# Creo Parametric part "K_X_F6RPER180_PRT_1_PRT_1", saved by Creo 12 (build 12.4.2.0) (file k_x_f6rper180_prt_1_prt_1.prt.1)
Units: Custom; MM, KILOGRAM, SECS

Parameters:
  PTC_WM_ITERATION = "0"
  PTC_WM_VERSION = "-.0"
  PTC_WM_LIFECYCLE_STATE = "In Work"
  PTC_WM_LIFECYCLE = "MO_CADDocument"
  PTC_WM_CREATED_BY = "Maximilian Roepper (Z0017RMS: MO)"
  PTC_WM_CREATED_ON = "18-Sep-26 11:36:42 AM"
  PTC_WM_MODIFIED_BY = "Maximilian Roepper (Z0017RMS: MO)"
  PTC_WM_MODIFIED_ON = "18-Sep-26 11:36:46 AM"
  PDMLINKNUMBER = "PDM000071454890"
  PTC_WM_NAME = "k_x_f6rper180_prt_1_prt_1.prt"
  PTC_WM_NUMBER = "PDM000071454890"

Other parameters: WEIGHT, WEIGHT_FACTOR, WEIGHT_ADD, _MASS_TEMP, _DIFF_TEMP, MC_ERRORS, SUPPLIER

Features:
  1. coordinate system
  2. datum plane "PRT_YZ"
  3. datum plane "PRT_XY"
  4. datum plane "PRT_XZ"
  5. coordinate system
  6. datum axis
  7. datum axis
  8. datum axis
  9. coordinate system
  10. imported feature
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
Other named items: PRT, SIEMENS_MO, DRW_VIEW_ORG, PRT_X, PRT_Y, PRT_Z, CS0, ROUGH_GROB

Layers: 00_STD_CSYS-KSYS, 01_STD_PLANES-EBENEN, 02_STD_AXES-ACHSEN, 03_STD_CSYS-KSYS, 24_IMPORT_FEAT-IMPORT_KE

Surfaces: 7 plane, 6 tabulated cylinder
